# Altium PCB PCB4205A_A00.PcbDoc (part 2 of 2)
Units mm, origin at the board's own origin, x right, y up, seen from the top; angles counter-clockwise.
Board outline 30 x 60 mm, 4 copper layers (Top Layer, Signal Layer 2, Signal Layer 3, Bottom Layer), stack 1.526 mm thick; 55 components, 66 nets, 233 pads, 356 vias.
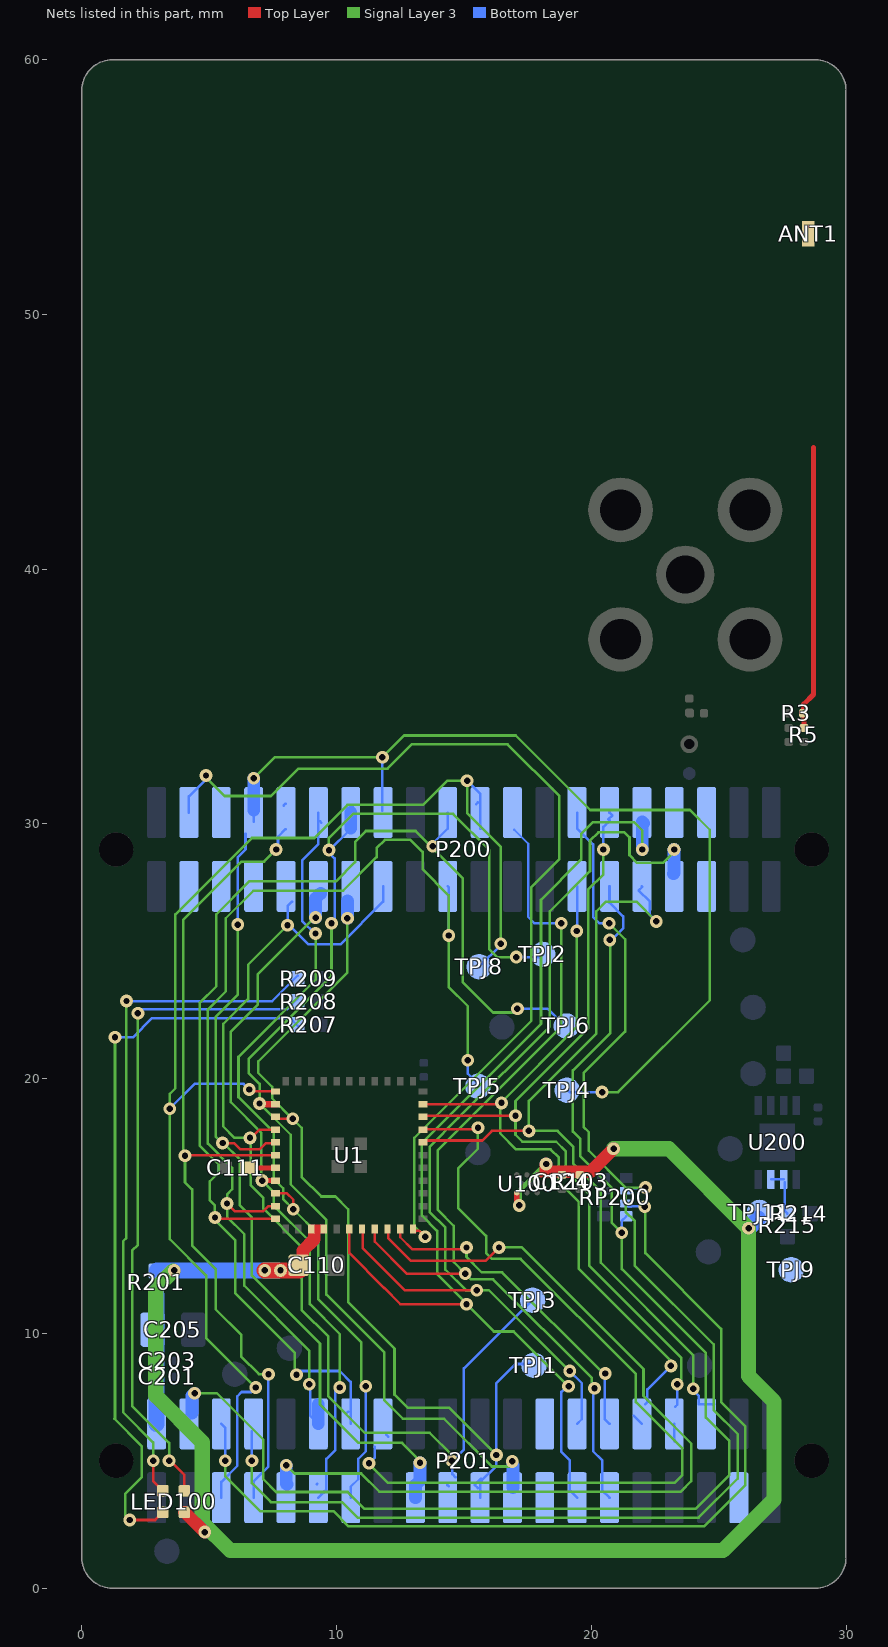
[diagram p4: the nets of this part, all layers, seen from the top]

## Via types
v1: diameter 0.5, hole 0.25, Top Layer to Bottom Layer, tented both sides, 356 vias

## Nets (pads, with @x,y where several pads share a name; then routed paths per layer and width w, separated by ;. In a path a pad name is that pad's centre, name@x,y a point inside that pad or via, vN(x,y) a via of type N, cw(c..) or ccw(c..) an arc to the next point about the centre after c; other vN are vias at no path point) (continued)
MODULE_PC06: P200.31 P201.36 U1.40 | length 33.3
  Top Layer w0.1: U1.40@13.475,17.575 13.5,17.55 13.525,17.575 15.725,17.575 16.1,17.95 v1(17.55,17.95)
  Signal Layer 3 w0.1: v1(22.55,26.175) 21.775,26.95 20.575,26.95 20.2,26.575 20.2,21.775 17.55,19.125 v1(17.55,17.95) 18.675,17.95 19.288,17.337 19.288,16.662 20.375,15.575 20.375,12.775 24,9.15 v1(24,7.825)
  Bottom Layer w0.1: P200.31@21.985,27.55 22,27.535 21.857,27.393 22.3,26.95 22.3,26.425 v1(22.55,26.175) ; v1(24,7.825) 24,7.775 24.225,7.55 24.225,7.225 P201.36@24.825,7.225
MODULE_PC07: P201.16 U1.41 | length 34.2
  Top Layer w0.1: U1.41@13.4,18 13.475,18 13.451,18.024 15.574,18.024 15.55,18.049 v1(15.55,18.075)
  Signal Layer 3 w0.1: v1@11.25,4.9 12.017,4.133 23.258,4.133 23.575,4.45 23.575,5.475 21.75,7.3 21.75,8.4 17.225,12.925 16.1,12.925 15.875,13.15 15.875,13.825 14.775,14.925 14.775,16.475 15.55,17.25 v1(15.55,18.075)
  Bottom Layer w0.1: v1(11.275,4.9) 11.5,5.125 P201.16@11.5,5.55 ; P201.16@11.95,6.025 P201.16@12.025,5.95
MODULE_PC08: P200.30 P201.34 U1.42 | length 33
  Top Layer w0.1: U1.42@13.45,18.5 13.5,18.55 16.9,18.55 17.025,18.675 v1(17.025,18.55)
  Signal Layer 3 w0.1: v1(20.475,29) 20.475,28.025 19.875,27.425 19.875,21.975 17.025,19.125 v1(17.025,18.55) 17.025,17.8 17.3,17.525 18.625,17.525 19,17.15 19,16.375 19.925,15.45 19.925,12.65 23.525,9.05 23.525,8.15 v1(23.375,8)
  Bottom Layer w0.1: v1(20.475,29) 20.475,29.89 20.725,30.14 20.675,30.19 20.825,30.34 P200.30@20.715,30.45 ; P201.34@23.255,5.77 P201.34@23.255,6.45 ; P201.34@23.3,7.125 23.375,7.2 v1(23.375,8)
MODULE_PC09: P200.27 P201.32 U1.43 | length 29
  Top Layer w0.1: U1.43@13.4,19 16.375,19 v1@16.425,19.05
  Signal Layer 3 w0.1: v1(16.475,19.05) 16.425,19 16.425,17.85 17.05,17.225 18.4,17.225 18.725,16.9 18.725,15.95 19.5,15.175 19.5,12.55 23.125,8.925 v1(23.125,8.725) ; v1@16.475,19.075 19.425,22.025 v1(19.425,25.8)
  Bottom Layer w0.1: v1(19.425,25.8) 19.445,25.82 P200.27@19.445,27.55 ; P201.32@21.675,6.76 P201.32@21.985,6.45 ; P201.32@22.125,7.225 22.2,7.3 22.2,7.8 v1(23.125,8.725)
MODULE_PD00: P200.4 U1.33 | length 38
  Top Layer w0.1: U1.33@13.075,13.975 13.125,14.025 13.25,14.025 v1(13.475,13.8)
  Signal Layer 3 w0.1: v1(4.875,31.902) 4.875,31.825 5.6,31.1 7.425,31.1 8.5,32.175 12,32.175 12.95,33.125 16.718,33.125 18.75,31.093 18.75,28.625 17.65,27.525 17.65,22.275 13.05,17.675 13.05,14.225 v1@13.45,13.825
  Bottom Layer w0.1: P200.4@4.205,30.45 4.205,31.08 4.875,31.75 v1(4.875,31.902)
MODULE_PD01: P201.30 U1.32 | length 13.1
  Top Layer w0.1: U1.32@12.5,14.1 12.5,13.775 12.975,13.3 15.025,13.3 v1(15.1,13.375)
  Signal Layer 3 w0.1: v1(15.1,13.375) 15.1,13 15.7,12.4 16.5,12.4 20.475,8.425 v1(20.55,8.425)
  Bottom Layer w0.1: v1(20.55,8.425) 20.55,8.5 20.526,8.524 20.526,6.639 P201.30@20.715,6.45
MODULE_PD02: P201.9 U1.31 | length 35.5
  Top Layer w0.1: U1.31@12.075,14.05 12.025,14 12.025,13.75 12.925,12.85 15.85,12.85 v1(16.375,13.375)
  Signal Layer 3 w0.1: v1(8.025,4.825) 8.35,4.5 10.967,4.5 11.675,3.792 23.517,3.792 23.925,4.2 23.925,5.675 22.05,7.55 22.05,8.6 17.275,13.375 v1(16.375,13.375)
  Bottom Layer w0.1: P201.9@7.975,4 P201.9@8.05,4.075
  Bottom Layer w0.5: v1(8.025,4.825) 8.025,4.1 P201.9@8.05,4.075
MODULE_PD03: P200.24 P201.29 U1.30 | length 37.6
  Top Layer w0.1: U1.30@11.5,14.1 11.5,13.6 12.75,12.35 v1@15.025,12.35
  Signal Layer 3 w0.1: v1@18.825,26.025 18.825,22.05 13.975,17.2 13.975,14.85 14.6,14.225 14.6,12.8 v1(15.05,12.35) 15.275,12.125 16.15,12.125 20.025,8.25 20.025,8.05 20.175,7.9 v1(20.126,7.851)
  Bottom Layer w0.1: P200.24@16.975,29.775 17.525,29.225 17.525,26.35 17.775,26.1 v1(18.825,26.1) ; v1(20.126,7.851) v1@20.126,7.75 ; v1@20.15,7.725 v1@20.126,7.75 ; P201.29@20.715,3.55 20.425,3.84 20.425,5.025 20.075,5.375 20.075,7.801 v1@20.126,7.75
MODULE_PD04: P200.33 P201.28 U1.29 | length 40.2
  Top Layer w0.1: U1.29@11.025,14.1 11.025,13.35 12.675,11.7 v1(15.5,11.7)
  Signal Layer 3 w0.1: v1(19.15,8.525) 15.975,11.7 v1(15.5,11.7) 15.075,11.7 14.275,12.5 14.275,14.15 13.65,14.775 13.65,17.325 14.775,18.45 18.375,22.05 18.375,26.575 19.95,28.15 19.95,29.35 20.275,29.675 21.3,29.675 21.5,29.475 21.5,28.775 21.8,28.475 22.816,28.475 v1@23.25,28.909 ; v1@23.225,28.875 23.25,28.9 v1@23.25,28.909 ; v1(23.25,29) v1@23.25,28.909 ; v1@23.295,28.955 v1@23.25,28.909
  Bottom Layer w0.1: v1(19.15,8.525) 19.625,8.05 19.625,6.63 P201.28@19.445,6.45
  Bottom Layer w0.5: P200.33@23.225,28.05 23.25,28.075 v1(23.25,29)
MODULE_PD05: P200.32 P201.27 U1.28 | length 43.1
  Top Layer w0.1: U1.28@10.5,14.1 10.5,13.15 11.863,11.788 11.875,11.775 12.5,11.15 v1(15.1,11.15)
  Signal Layer 3 w0.1: v1@19.238,7.788 16.95,10.075 16.175,10.075 v1(15.1,11.15) 15.1,11.175 13.95,12.325 13.95,14.025 13.35,14.625 13.35,17.475 14.625,18.75 18.025,22.15 18.025,27.025 19.6,28.6 19.6,29.6 20.075,30.075 21.675,30.075 22,29.75 v1(22,29)
  Bottom Layer w0.1: v1(19.109,7.925) 19.05,7.925 18.825,7.7 18.825,5.35 19.15,5.025 19.15,3.845 P201.27@19.445,3.55 ; P200.32@21.95,30.125 P200.32@22,30.075
  Bottom Layer w0.5: v1(22,29) 22,29.975 22.05,30.025 P200.32@22,30.075
N16865893: ANT1.1 R3.2 R5.1 | length 11.1
  Top Layer w0.2: R5.1@28.35,33.8 28.35,34.34 28.34,34.35 28.34,34.7 28.72,35.08 28.72,44.77
N16878557: LED100.2 R207.2 | length 28.9
  Top Layer w0.1: v1(1.875,2.675) 2.875,2.675 LED100.2@3.175,2.975 LED100.2@3.175,3.091
  Signal Layer 3 w0.1: v1(1.3,21.626) 1.3,6.675 1.275,6.65 2.35,5.575 2.35,4.35 1.7,3.7 1.7,2.85 v1(1.875,2.675)
  Bottom Layer w0.1: v1(1.3,21.626) 2.001,21.626 2.75,22.375 8.175,22.375 R207.2@8.475,22.075
N16878561: LED100.3 R209.2 | length 27.1
  Top Layer w0.1: v1(2.8,5) 2.8,4.2 LED100.3@3.175,3.825
  Signal Layer 3 w0.1: v1(1.75,23.05) 1.75,13.75 1.625,13.625 1.625,6.9 2.8,5.725 v1(2.8,5)
  Bottom Layer w0.1: v1(1.75,23.05) 7.475,23.05 R209.2@8.475,24.05
N16878567: LED100.4 R208.2 | length 26.2
  Top Layer w0.1: v1(3.425,5) 3.475,5 4.025,4.45 LED100.4@4.025,3.825
  Signal Layer 3 w0.1: v1(2.2,22.575) 2.2,13.475 1.975,13.25 1.975,7.15 3.425,5.7 v1(3.425,5)
  Bottom Layer w0.1: v1@2.175,22.575 2.325,22.725 8.05,22.725 R208.2@8.45,23.125
N16881966: R214.2 R215.1 U200.2 U200.3 | length 1.7
  Bottom Layer w0.1: U200.3@27.075,16.05 U200.2@27.55,16.05 ; U200.2@27.6,15.925 27.6,14.8 R214.2@27.7,14.7
N17193357: C111.1 U1.18 | length 1
  Top Layer w0.2: C111.1@6.575,16.475 6.6,16.5 U1.18@7.6,16.5
TP_TCK_SWCLK: P200.14 P201.23 TPJ2.1 U1.13 | length 49.4
  Top Layer w0.25: v1@6.975,18.975 7,19 U1.13@7.6,19
  Signal Layer 3 w0.1: v1(9.7,28.975) 9.7,29.45 10.65,30.4 14.575,30.4 16,28.975 16,25.075 16.3,24.775 v1(17.05,24.775) ; v1(9.8,26.1) 9.8,24.025 6.55,20.775 6.55,20.225 6.975,19.8 v1(6.975,19.025) 8.2,17.8 8.2,15.85 9.6,14.45 9.6,11.525 11.875,9.25 11.875,7.375 12.6,6.65 14.225,6.65 16.1,4.775 16.9,4.775 v1(16.9,4.975)
  Bottom Layer w0.1: v1(9.8,26.1) 9.925,26.225 9.925,28.65 9.7,28.875 v1(9.7,28.975) 9.725,28.975 P200.14@10.525,29.775 ; P200.14@10.525,30.6 P200.14@10.625,30.7 ; P200.14@10.555,29.82 P200.14@10.555,29.83 ; P201.23@16.85,3.875 P201.23@16.925,3.95 ; v1(16.9,4.975) 16.825,4.975 16.8,4.95 v1@16.925,4.825 ; v1(17.05,24.775) 17.995,24.775 TPJ2.1@18.1,24.88
  Bottom Layer w0.5: P200.14@10.555,29.83 P200.14@10.555,30.45 ; P201.23@16.925,3.95 v1@16.925,4.825
TP_TDI: P200.8 P200.16 P201.17 TPJ4.1 U1.16 | length 71
  Top Layer w0.1: v1(5.525,17.475) 5.975,17.475 6.225,17.225 6.975,17.225 7.225,17.475 7.575,17.475 U1.16@7.6,17.5
  Signal Layer 3 w0.1: v1(6.125,26.05) 6.125,23.3 5.25,22.425 5.25,17.725 5.525,17.45 v1(5.525,17.475) 5.55,17.475 6.2,16.825 6.2,15.025 6.675,14.55 6.675,12.275 9.35,9.6 9.35,7.21 10.86,5.7 12.575,5.7 13.275,5 v1(13.275,4.925) ; v1(6.75,31.8) 7.575,32.625 v1(11.8,32.625) 12.65,33.475 17.034,33.475 19.959,30.55 23.875,30.55 24.65,29.775 24.65,23.075 21.05,19.475 v1(20.425,19.475)
  Bottom Layer w0.1: v1(6.125,26.05) 6.125,28.7 6.425,29 P200.8@6.425,29.625 ; P200.8@6.745,30.08 P200.8@6.745,30.45 ; P200.8@6.75,30.5 6.725,30.525 P200.8@6.75,30.549 ; P200.16@11.8,30.525 v1(11.8,32.625) ; TPJ4.1@19.075,19.55 19.15,19.475 v1(20.425,19.475)
  Bottom Layer w0.5: P200.8@6.75,30.549 v1(6.75,31.8) ; P201.17@13.095,3.55 13.095,4.045 13.275,4.225 v1(13.275,4.925)
TP_TDO_SWO: P200.9 P200.15 P201.19 TPJ3.1 U1.15 | length 44.3
  Top Layer w0.1: v1(6.6,17.675) 6.625,17.675 6.588,17.638 6.6,17.625 6.975,18 U1.15@7.6,18
  Signal Layer 3 w0.1: v1@6.6,17.65 v1(6.6,17.675) v1@6.6,17.85 ; v1(8.075,26.025) 6.525,24.475 6.525,23.125 5.55,22.15 5.55,18.125 6,17.675 6.425,17.675 v1@6.6,17.85 ; v1(14.526,5) 14.526,5.224 13.65,6.1 11.1,6.1 9.675,7.525 9.675,9.875 8.625,10.925 8.625,13.4 7.125,14.9 7.125,15.325 6.625,15.825 6.625,17.875 v1@6.6,17.85
  Bottom Layer w0.1: v1(8.075,26.025) v1@8.075,26.1 ; P200.9@8.25,26.95 8.075,26.775 v1@8.075,26.1 ; P200.15@11.825,27.55 11.825,26.95 10.15,25.275 8.9,25.275 v1@8.075,26.1 ; P201.19@14.35,4.05 P201.19@14.4,4 ; v1(14.526,5) v1@14.6,5 ; P201.19@14.675,4.35 14.55,4.475 14.55,4.95 v1@14.6,5 ; TPJ3.1@17.625,11.25 15,8.625 15,5.45 14.65,5.1 14.75,5 v1@14.6,5
TP_TMS_SWDIO: P200.13 P201.21 TPJ1.1 U1.14 | length 36.5
  Top Layer w0.1: U1.14@7.6,18.5 7.675,18.425 v1(8.275,18.425) v1@8.45,18.425
  Signal Layer 3 w0.1: v1(10.426,26.301) 10.426,24.176 6.925,20.675 6.925,20.231 7.475,19.681 7.475,19.225 v1(8.275,18.425) 8.625,18.075 8.625,16.15 9.4,15.375 9.95,15.375 10.45,14.875 10.45,11.225 12.275,9.4 12.275,7.6 12.8,7.075 14.426,7.075 v1(16.276,5.225)
  Bottom Layer w0.1: P200.13@10.45,27.1 P200.13@10.475,27.125 ; P201.21@15.55,3.925 15.425,4.05 P201.21@15.675,4.3 ; P201.21@15.635,3.55 15.635,4.16 16.276,4.801 16.276,5.101 v1(16.276,5.225) ; v1@16.275,5.1 16.275,8.05 17.025,8.8 17.725,8.8 TPJ1.1@17.75,8.775
  Bottom Layer w0.5: v1(10.426,26.301) P200.13@10.426,26.976
TP_VCOM_RTS: P200.22 P201.5 TPJ8.1 U1.12 | length 54.1
  Top Layer w0.1: v1(6.575,19.575) 6.65,19.5 U1.12@7.6,19.5
  Signal Layer 3 w0.1: v1(6.825,7.875) 4.875,9.825 4.875,12.275 3.45,13.7 v1(3.45,18.825) 3.45,19.4 3.675,19.625 3.675,26.45 6.675,29.45 9.125,29.45 10.425,30.75 13.4,30.75 14.35,31.7 v1(15.125,31.7) 15.125,30.425 16.45,29.1 16.45,25.475 16.275,25.3 v1(16.45,25.3)
  Bottom Layer w0.1: v1(3.45,18.825) 4.425,19.8 6.35,19.8 v1(6.575,19.575) ; P201.5@5.475,3.55 5.475,4.175 6.1,4.8 6.1,7.525 6.275,7.7 6.65,7.7 v1(6.825,7.875) ; v1(15.125,31.7) 15.635,31.19 P200.22@15.635,30.45 P200.22@15.635,29.81 ; P200.22@15.475,30.775 P200.22@15.55,30.85 ; TPJ8.1@15.575,24.4 TPJ8.1@15.587,24.412 ; TPJ8.1@15.6,24.4 16.45,25.25 v1(16.45,25.3)
TP_VCOM_RX: P200.20 P201.14 TPJ6.1 U1.22 | length 49.3
  Top Layer w0.1: v1@5.275,14.5 U1.22@7.6,14.5
  Signal Layer 3 w0.1: v1@8.35,8.45 8.35,9.25 6.025,11.575 6.025,13.65 5.225,14.45 v1(5.225,14.55) 5.225,15.025 5.025,15.225 5.025,15.975 5.375,16.325 5.375,16.625 4.625,17.375 4.625,22.975 5.275,23.625 5.275,26.45 6.57,27.745 9.97,27.745 10.725,28.5 10.725,29.3 11.15,29.725 13.1,29.725 14.95,27.875 14.95,23.8 16.15,22.6 16.95,22.6 v1(17.1,22.75)
  Bottom Layer w0.1: v1(8.425,8.375) 8.575,8.525 10.125,8.525 10.555,8.095 P201.14@10.555,6.45 ; P201.14@10.4,6.875 P201.14@10.45,6.925 ; v1(13.775,29.125) 13.775,29.23 14.365,29.82 P200.20@14.365,30.45 ; v1(17.1,22.75) 18.275,22.75 18.925,22.1 TPJ6.1@18.925,22.05
TP_VCOM_TX: P200.19 P201.12 TPJ5.1 U1.21 | length 46.5
  Top Layer w0.1: v1@5.725,15.075 6,14.8 7.125,14.8 7.325,15 U1.21@7.6,15
  Signal Layer 3 w0.1: v1@8.8,7.844 8.925,7.969 v1(8.925,8) 8.925,9.325 6.375,11.875 6.375,13.9 5.7,14.575 v1(5.7,15.1) 5.7,15.459 5.9,15.659 5.9,16.5 4.95,17.45 4.95,22.725 5.65,23.425 5.65,26.3 6.73,27.38 10.255,27.38 11.575,28.7 11.575,29.05 11.9,29.375 12.9,29.375 13.375,28.9 13.375,28.225 14.4,27.2 v1(14.4,25.625) 14.4,23.6 15.15,22.85 v1(15.15,20.725)
  Bottom Layer w0.1: v1@8.95,7.9 8.975,7.875 8.975,6.76 P201.12@9.285,6.45 ; P200.19@14.365,27.55 14.4,27.515 v1(14.4,25.625) ; v1(15.15,20.725) 15.15,20.2 15.6,19.75 TPJ5.1@15.55,19.7
  Bottom Layer w0.5: P201.12@9.285,6.45 P201.12@9.285,7.216
USB_VBUS: P200.35
USB_VREG: P200.36
VMCU: C110.1 C124.1 LED100.1 R103.2 R201.2 TPJ11.1 U1.25 U1.26 U100.A1 U100.E3 | length 68.6
  Top Layer w0.2: U100.E3@17.075,15.525 17.075,15.125 v1(17.175,15.025) ; U100.A1@17.875,16.225 18.425,16.225
  Top Layer w0.35: U1.25@9.05,14.1 U1.26@9.45,14.1
  Top Layer w0.5: LED100.1@4.025,2.975 4.05,2.975 v1(4.825,2.2) ; C110.1@8.675,12.625 8.675,13.25 9.125,13.7 U1.25@9.125,14.025 ; v1(18.225,16.65) 18.225,16.35 19.55,16.35 19.975,16.35 v1(20.875,17.25)
  Top Layer w0.635: v1(7.175,12.475) v1(7.8,12.475) 8.55,12.475 C110.1@8.575,12.5
  Signal Layer 3 w0.2: v1(17.175,15.025) 17.175,15.6 v1(18.225,16.65)
  Signal Layer 3 w0.6: v1@3.575,12.45 2.9,11.775 2.9,7.556 4.725,5.731 4.725,2.575 5.825,1.475 25.175,1.475 27.175,3.475 27.175,7.325 26.175,8.325 v1(26.175,14.125) 23.05,17.25 v1(20.875,17.25)
  Bottom Layer w0.635: R201.2@2.95,12.475 v1(3.625,12.475) v1(7.175,12.475) v1@7.726,12.475 ; v1(26.175,14.125) 26.225,14.175 TPJ11.1@26.55,14.5
VMCU_IN: C201.1 C203.1 C205.1 P201.2 R201.1 | length 5.1
  Bottom Layer w0.635: P201.2@2.935,6.45 R201.1@2.935,11.515
VRF: TPJ9.1
WSTK_F15: P200.28 P201.8 RP200.6 | length 54.2
  Signal Layer 3 w0.1: v1(6.675,5) 6.675,4.125 7.425,3.375 10.217,3.375 10.825,2.767 24.217,2.767 25.75,4.3 25.75,6.05 24.8,7 24.8,9.575 21.7,12.675 21.7,14.425 21.35,14.775 21.35,15.725 ; v1(20.7,26.1) 20.75,26.1 20.725,26.075 21.325,25.475 21.325,21.85 19.7,20.225 19.7,18.1 19.9,17.9 19.9,17.175 21.35,15.725 ; v1@22.1,15.725 21.35,15.725
  Bottom Layer w0.1: v1(6.675,5) P201.8@6.675,6.149 ; P200.28@19.445,30.45 19.445,29.83 20.075,29.2 20.075,26.35 20.325,26.1 v1(20.7,26.1) ; RP200.6@21.375,15.6 21.475,15.7 22,15.7 v1@22.1,15.8
  other v1: 22.125,15.725
WSTK_F16: P200.29 P201.4 RP200.8 | length 52.5
  Signal Layer 3 w0.1: v1(4.425,7.65) 5.3,7.65 7.125,5.825 7.125,4.275 7.625,3.775 10.433,3.775 11.1,3.108 24.083,3.108 25.425,4.45 25.425,5.775 24.5,6.7 24.5,9.225 21.2,12.525 v1(21.2,13.95) 21.2,14.1 21.125,14.025 20.8,14.35 20.8,15.725 19.575,16.95 19.575,17.625 19.275,17.925 19.275,20.325 20.75,21.8 20.75,25.425 v1@20.775,25.45
  Bottom Layer w0.1: P200.29@20.715,27.55 20.715,26.91 21.25,26.375 21.25,25.9 20.8,25.45 v1@20.775,25.45 ; 21.2,14.2 21.2,14.425 RP200.8@21.375,14.6
  Bottom Layer w0.5: P201.4@4.325,6.875 4.325,7.55 v1(4.425,7.65)
  other v1: 20.725,25.45
WSTK_F21: P200.34
WSTK_P3: P201.6 RP200.7 | length 37.3
  Signal Layer 3 w0.1: v1(5.625,5) 5.625,4.4 7,3.025 9.875,3.025 10.475,2.425 24.425,2.425 26.05,4.05 26.05,6.35 25.1,7.3 25.1,10.175 22.125,13.15 22.125,14.825 v1@22.2,14.9
  Bottom Layer w0.1: P201.6@5.475,6.45 5.625,6.3 v1@5.625,5.05 ; RP200.7@21.375,15.1 21.475,15 v1@22.125,15
  other v1: 22.1,14.975
WSTK_P4: P200.10 P201.7 U1.17 | length 34.2
  Top Layer w0.1: v1(4.05,16.975) 4.075,17 U1.17@7.6,17
  Signal Layer 3 w0.1: v1(7.325,8.4) 6.95,8.4 6.25,9.1 6.25,9.95 5.25,10.95 5.25,12.525 4.325,13.45 4.325,15.65 4.05,15.925 v1(4.05,16.975) 3.975,17.05 3.975,26.225 6.275,28.525 7.15,28.525 v1(7.625,29)
  Bottom Layer w0.1: P201.7@6.745,3.55 6.745,4.195 7.325,4.775 v1(7.325,8.4) ; v1(7.625,29) 7.625,28.85 7.7,28.925 7.7,29.5 P200.10@8,29.8 ; P200.10@7.925,30.725 P200.10@8,30.8
WSTK_P10: P200.12 P201.13 U1.20 | length 32.3
  Top Layer w0.1: U1.20@7.55,15.5 U1.20@7.575,15.525 ; U1.20@7.6,15.5 8.05,15.5 8.3,15.25 v1(8.3,14.875)
  Signal Layer 3 w0.1: v1(9.175,25.7) 9.175,23.884 6.15,20.859 6.15,19.275 7.525,17.9 7.525,16.075 7.9,15.7 7.9,15.275 v1(8.3,14.875) 9.275,13.9 9.275,11.35 10.975,9.65 10.975,8.1 v1(11.15,7.925)
  Bottom Layer w0.1: v1(9.175,25.7) 9.175,25.675 8.65,26.2 8.65,28.575 9.285,29.21 P200.12@9.285,30.45 ; P200.12@9.35,30.1 P200.12@9.4,30.05 ; P201.13@10.555,3.55 10.555,3.98 10.85,4.275 10.85,5.075 11.15,5.375 v1(11.15,7.925)
WSTK_P22: P201.25
WSTK_P23: P201.26
WSTK_P34: P201.37
WSTK_P36: P200.3
WSTK_P38: P200.5
WSTK_P39: P200.6
WSTK_P40: P200.7
WSTK_P44: P200.11 P201.11 U1.19 | length 28.1
  Top Layer w0.1: v1(7.075,16) v1@7.2,16 ; U1.19@7.6,16 7.625,16 U1.19@7.6,16.025
  Top Layer w0.2: v1@7.2,16 U1.19@7.6,16
  Signal Layer 3 w0.1: v1@9.125,26.325 6.9,24.1 6.9,22.9 5.85,21.85 5.85,19.075 7.05,17.875 7.05,16.15 7.075,16.125 v1(7.075,16) 7.525,15.55 7.525,15.025 8.95,13.6 8.95,11.15 10.125,9.975 v1(10.125,7.875) ; v1(9.175,26.326) v1(9.175,26.326)
  Bottom Layer w0.1: P201.11@9.225,4.075 P201.11@9.25,4.1 ; P201.11@9.285,3.55 9.6,3.865 9.6,5.075 9.95,5.425 9.95,7.9 9.975,7.875 v1(10.125,7.875) ; P200.11@9.3,27.35 P200.11@9.375,27.275
  Bottom Layer w0.5: v1(9.175,26.326) 9.175,27.075 P200.11@9.375,27.275
pads on no net: P200.M1 P200.M2 P201.40 P201.M1 P201.M2 RP200.4 RP200.5 TPJ18.1 TPJ19.1 TPJ20.1 U1.24 U100.C1 U200.9

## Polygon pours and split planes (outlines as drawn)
GND on Signal Layer 3 "GND_L3" (solid, remove dead copper, pour order 31): 0,35.3 19,35.3 19,43.8 cw(c19.7,43.8) 19.7,44.5 30,44.5 30,0 0,0
GND on Signal Layer 2 "GND_L2" (solid, remove dead copper, pour order 33): 0,35.3 19,35.3 19,43.8 cw(c19.7,43.8) 19.7,44.5 30,44.5 30,0 0,0
GND on Top Layer "GND_TOP" (solid, remove dead copper, pour order 35): 0,35.3 19,35.3 19,43.8 cw(c19.7,43.8) 19.7,44.5 29.95,44.5 30,0 0,0
GND on Bottom Layer "GND_Bottom" (solid, remove dead copper, pour order 24): 0,35.3 19,35.3 19,43.8 cw(c19.7,43.8) 19.7,44.5 30,44.5 30,0 0,0

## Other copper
Top Layer:
  rectangle net GND: 11.225,18.925 12.875,19.625
  rectangle net N16865893: 28.27,44.95 28.77,53.65
  region net N16865893: 28.27,45 28.27,44.95 28.82,44.4 28.82,44.95 28.77,45
  region net GND: 12.375,20.075 12.375,21.1 12.95,21.675 12.95,20.375 12.875,20.175 12.725,20.175 12.625,20.075
  region net GND: 11.375,20.075 11.275,20.175 11.275,20.672 11.167,20.78 11.167,21.558 11.625,21.1 11.625,20.075
Bottom Layer:
  pour cut-out: 19.7,31.55 20.45,31.55 20.45,31.05 19.7,31.05
  pour cut-out: 18.45,28.65 19.2,28.65 19.2,28.15 18.45,28.15
  pour cut-out: 17.175,31.55 17.925,31.55 17.925,31.05 17.175,31.05
  pour cut-out: 9.55,31.55 10.3,31.55 10.3,31.05 9.55,31.05
  pour cut-out: 10.825,2.95 11.575,2.95 11.575,2.45 10.825,2.45
  pour cut-out: 15.9,2.95 16.65,2.95 16.65,2.45 15.9,2.45
  pour cut-out: 22.038,7.55 24.413,7.55 24.413,7.05 22.038,7.05
  pour cut-out: 13.325,31.55 14.075,31.55 14.075,31.05 13.325,31.05
  pour cut-out: 14.675,29.85 15.425,29.85 15.425,29.35 14.675,29.35
  pour cut-out: 12.075,26.95 12.825,26.95 12.825,26.45 12.075,26.45
  pour cut-out: 12.8,29.025 13.55,29.025 13.55,28.525 12.8,28.525
  pour cut-out: 5.825,9.05 6.575,9.05 6.575,8.55 5.825,8.55
  pour cut-out: 5.725,2.95 6.475,2.95 6.475,2.45 5.725,2.45
  pour cut-out: 22.237,2.95 24.612,2.95 24.612,2.45 22.237,2.45
  pour cut-out: 12.1,31.55 12.85,31.55 12.85,31.05 12.1,31.05
  pour cut-out: 10.825,28.65 11.575,28.65 11.575,28.15 10.825,28.15
  pour cut-out: 23.845,33.935 cw(c23.845,33.135) 24.645,33.135 cw(c23.845,33.135) 23.845,32.335 cw(c23.845,33.135) 23.045,33.135 cw(c23.845,33.135)

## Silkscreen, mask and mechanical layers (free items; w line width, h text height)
Top Overlay:
  text "ZGM230S" at 0.95,56.9 h3.2
  text "868-915 MHz" at 1.1,54.5 h1.9
  text "14 dBm" at 1.1,52.5 h1.9
Bottom Overlay:
  text "PCB4205A Rev. A00" at 26.7,0.6 h1.52
Top Solder:
  the board outline again, w0.8
Bottom Solder:
  lines w0.8: 0,58.8 cw(c1.2,58.8) 1.2,60 28.8,60 cw(c28.8,58.8) 30,58.8 ; 0,58.9 0,1.2 ccw(c1.2,1.2) 1.2,0 28.8,0 ccw(c28.8,1.2) 30,1.2 30,58.9
BOARD OUTLINE 1:
  the board outline again, w0.1
Mechanical 11:
  the board outline again, w0.1
Mechanical 12:
  the board outline again, w0.1
Mechanical 15:
  lines w0.025: 69.971,-48.875 70.179,-48.875 ; 70.075,-48.979 70.075,-48.771
EXT_SILKP 20:
  lines w0.152: 3.95,11.925 3.95,11.625 4.25,11.625 ; 3.95,13.175 3.95,13.475 4.25,13.475 ; 4.075,21.65 4.075,21.35 4.375,21.35 ; 4.075,22 4.075,22.3 4.375,22.3 ; 4.6,11.625 4.9,11.625 4.9,11.925 ; 4.625,21.35 4.925,21.35 4.925,21.05 ; 4.9,12.175 4.9,12.475 5.2,12.475 ; 4.925,20.75 4.925,20.425 5.225,20.425 ; 5.5,12.475 5.825,12.475 5.825,12.775 ; 5.5,13.475 5.825,13.475 5.825,13.175 ; 5.625,20.425 5.925,20.425 5.925,20.75 ; 5.625,22.3 5.925,22.3 5.925,22 ; 21.075,13.25 21.075,12.95 21.375,12.95 ; 21.075,14.5 21.075,14.8 21.375,14.8 ; 21.725,12.95 22.025,12.95 22.025,13.25 ; 22.025,13.5 22.025,13.8 22.325,13.8 ; 22.625,13.8 22.95,13.8 22.95,14.1 ; 22.625,14.8 22.95,14.8 22.95,14.5
  lines w0.154: 1.5,38 1.5,37 2.5,37 ; 1.5,42 1.5,43 2.5,43 ; 19.5,37 20.5,37 20.5,38 ; 19.5,43 20.5,43 20.5,42
  text "BOARD INFO" at 20.55,43.35 h1.52
  text "Sensor Enable" at 9.45,22.85 h1.52
  text "ON" at 3.8,21.475 h1.14
  text "WSTK_P37" at 11.475,21.025 h1.14
  text "Disp Enable" at 25.275,15.125 h1.52
  text "ON" at 24.6,13.95 h1.14
  text "PAVDD" at 6.85,13.9 h1.52
  text "WSTK_P35" at 20.95,13.475 h1.14
  text "VDCDC" at 9.6,12.6 h1.14
  text "VMCU" at 3.825,12.15 h1.14
Mechanical 26:
  lines w0.2: -122.4,-40.25 -120.775,-40.25 ; -122.4,6.425 -120.775,6.425 ; -122.4,53.1 -120.775,53.1 ; -67.75,-88.5 -67.75,-86.9 ; -67.75,99.8 -67.75,101.4 ; -14.725,-88.5 -14.725,-86.9 ; -14.725,99.8 -14.725,101.4 ; 38.3,-88.5 38.3,-86.9 ; 38.3,99.8 38.3,101.4 ; 91.325,-88.5 91.325,-86.9 ; 91.325,99.8 91.325,101.4 ; 144.35,-40.225 145.975,-40.225 ; 144.35,6.45 145.975,6.45 ; 144.35,53.125 145.975,53.125 ; 145.975,-88.5 -122.4,-88.5 -122.4,101.4 145.975,101.4 145.975,-88.475 ; -120.775,-86.9 144.35,-86.9 144.35,99.8 -120.775,99.8 -120.775,-86.9
  text "5" at -94.425,100.325 h0.5
  text "4" at -41.4,100.3 h0.5
  text "3" at 11.625,100.3 h0.5
  text "2" at 64.65,100.3 h0.5
  text "1" at 117.775,100.3 h0.5
  text "D" at 145.025,76.2 h0.5
  text "D" at -121.725,76.175 h0.5
  text "C" at 145.025,29.5 h0.5
  text "C" at -121.725,29.475 h0.5
  text "B" at 145.025,-17.175 h0.5
  text "B" at -121.725,-17.2 h0.5
  text "A" at 145.025,-63.825 h0.5
  text "A" at -121.725,-63.85 h0.5
  text "5" at -94.425,-87.975 h0.5
  text "4" at -41.4,-88 h0.5
  text "3" at 11.625,-88 h0.5
  text "2" at 64.65,-88 h0.5
  text "1" at 117.775,-88 h0.5
Mechanical 27:
  drawing of 28 lines, arcs and shapes, not listed
  text "Board Title" at 74.75,-61.95 h2.5
  text "ZGM230S Radio Board" at 76.15,-67.5 h4
  text "Page Title" at 74.75,-71.675 h2.5
  text "Designed:" at 42.5,-75.425 h1.7
  text "Approved:" at 58.7,-75.425 h1.7
  text "Top Assembly" at 76.15,-75.575 h3.2
  text "ADS" at 44.025,-77.925 h2.2
  text "OLP" at 60.075,-77.925 h2.2
  text "Revision" at 132.65,-78.7 h1.7
  text "Document number" at 74.75,-78.975 h2.35
  text "Size" at 42.5,-80.175 h1.7
  text "BOM Doc. No:" at 47.425,-80.175 h1.7
  text ".BoardRevision" at 132.925,-81.75 h2.7
  text ".BoardName" at 76.15,-81.85 h3.2
  text "A4" at 43.075,-82.025 h2
  text "<>" at 48,-82.025 h2
  text "Design Created Date:" at 42.5,-84.375 h1.7
  text "Sheet Created Date:" at 74.175,-84.375 h1.7
  text "Sheet Modified Date:" at 102.6,-84.375 h1.7
  text "Sheet" at 132.65,-84.375 h1.7
  text "Monday, July 14, 2020" at 43.575,-86.325 h1.7
  text "Monday, July 13, 2020" at 75.3,-86.325 h1.7
  text "'.Print_Date'" at 103.725,-86.325 h1.7
  text "1" at 133.85,-86.325 h1.7
  text "of" at 136.975,-86.325 h1.7
  text "2" at 139.7,-86.325 h1.7
Mechanical 28:
  lines w0.2: -122.4,-40.25 -120.775,-40.25 ; -122.4,6.425 -120.775,6.425 ; -122.4,53.1 -120.775,53.1 ; -67.75,-88.5 -67.75,-86.9 ; -67.75,99.8 -67.75,101.4 ; -14.725,-88.5 -14.725,-86.9 ; -14.725,99.8 -14.725,101.4 ; 38.3,-88.5 38.3,-86.9 ; 38.3,99.8 38.3,101.4 ; 91.325,-88.5 91.325,-86.9 ; 91.325,99.8 91.325,101.4 ; 144.35,-40.225 145.975,-40.225 ; 144.35,6.45 145.975,6.45 ; 144.35,53.125 145.975,53.125 ; 145.975,-88.5 -122.4,-88.5 -122.4,101.4 145.975,101.4 145.975,-88.475 ; -120.775,-86.9 144.35,-86.9 144.35,99.8 -120.775,99.8 -120.775,-86.9
  text "5" at -94.1,100.325 h0.5
  text "4" at -41.075,100.3 h0.5
  text "3" at 11.95,100.3 h0.5
  text "2" at 64.975,100.3 h0.5
  text "1" at 117.95,100.3 h0.5
  text "D" at 145.35,76.2 h0.5
  text "D" at -121.4,76.175 h0.5
  text "C" at 145.35,29.5 h0.5
  text "C" at -121.4,29.475 h0.5
  text "B" at 145.35,-17.175 h0.5
  text "B" at -121.4,-17.2 h0.5
  text "A" at 145.35,-63.825 h0.5
  text "A" at -121.4,-63.85 h0.5
  text "5" at -94.1,-87.975 h0.5
  text "4" at -41.075,-88 h0.5
  text "3" at 11.95,-88 h0.5
  text "2" at 64.975,-88 h0.5
  text "1" at 117.95,-88 h0.5
Mechanical 29:
  drawing of 28 lines, arcs and shapes, not listed
  text "Board Title" at -51.175,-61.95 h2.5
  text "ZGM230S Radio Board" at -52.575,-67.5 h4
  text "Page Title" at -51.175,-71.675 h2.5
  text "Approved:" at -35.125,-75.425 h1.7
  text "Designed:" at -18.925,-75.425 h1.7
  text "Bottom Assembly" at -52.575,-75.575 h3.2
  text "OLP" at -36.5,-77.925 h2.2
  text "ADS" at -20.45,-77.925 h2.2
  text "Revision" at -109.075,-78.7 h1.7
  text "Document number" at -51.175,-78.975 h2.35
  text "BOM Doc. No:" at -23.85,-80.175 h1.7
  text "Size" at -18.925,-80.175 h1.7
  text ".BoardRevision" at -109.339,-81.75 h2.7
  text ".BoardName" at -52.575,-81.85 h3.2
  text "<>" at -24.425,-82.025 h2
  text "A4" at -19.5,-82.025 h2
  text "Sheet" at -109.075,-84.375 h1.7
  text "Sheet Modified Date:" at -79.025,-84.375 h1.7
  text "Sheet Created Date:" at -50.6,-84.375 h1.7
  text "Design Created Date:" at -18.925,-84.375 h1.7
  text "2" at -116.125,-86.325 h1.7
  text "of" at -113.4,-86.325 h1.7
  text "2" at -110.275,-86.325 h1.7
  text "'.Print_Date'" at -80.15,-86.325 h1.7
  text "Monday, July 13, 2020" at -51.725,-86.325 h1.7
  text "Monday, July 13, 2020" at -20,-86.325 h1.7
Mechanical 30:
  lines w0.2: -126.75,-94.975 -126.75,105.5 156.75,105.5 156.75,-94.975 -126.75,-94.975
